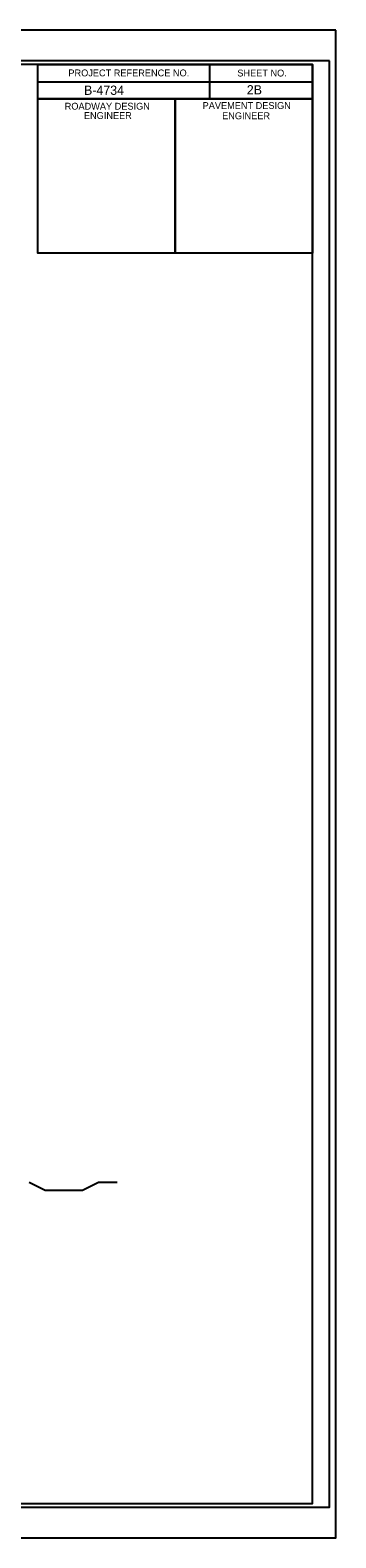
# Model space of a CAD drawing. Extents: x 1818040 to 1825768, y 638918 to 648046.
# Drawn here: x 1821878 to 1822100, y 642603 to 643703 of the extents above; entities that cross this region are included whole.
import ezdxf

# ---------------------------------------------------------------- set-up
doc = ezdxf.new("R2010")
doc.units = 0
for name, color, linetype in [('Sheet Data Field CELL', 7, 'Continuous'), ('Sheet Plot Border Inside CELL', 7, 'Continuous'), ('Sheet Plot Border Outside CELL', 7, 'Continuous'), ('Sheet Typical CELL', 7, 'Continuous'), ('Typical Slope Point Local CELL', 7, 'Continuous')]:
    doc.layers.add(name, color=color, linetype=linetype)

msp = doc.modelspace()

# ---------------------------------------------------------------- linework, layer by layer
at = {"layer": 'Sheet Plot Border Inside CELL'}
msp.add_lwpolyline([(1822095.8, 643680.8), (1820429.3, 643680.8), (1820429.3, 642625.7), (1822095.8, 642625.7)], close=True, dxfattribs=at)
at = {"layer": 'Sheet Plot Border Outside CELL'}
msp.add_lwpolyline([(1822100.3, 643703.3), (1820416.3, 643703.3), (1820416.3, 642603.3), (1822100.3, 642603.3)], close=True, dxfattribs=at)
at = {"layer": 'Sheet Typical CELL'}
for p, q in [((1822100.3, 643703.3), (1820416.3, 643703.3)), ((1822008.3, 643678.2), (1822008.3, 643653.2)), ((1821883.3, 643665.7), (1822083.3, 643665.7)), ((1821983.3, 643653.2), (1821983.3, 643540.8)), ((1820416.3, 642603.3), (1822100.3, 642603.3))]:
    msp.add_line(p, q, dxfattribs=at)
for points in [[(1822083.3, 643678.3), (1820583.3, 643678.3), (1820583.3, 642628.3), (1822083.3, 642628.3)], [(1821883.3, 643678.3), (1822083.3, 643678.3), (1822083.3, 643653.2), (1821883.3, 643653.2)], [(1821883.3, 643653.2), (1821983.3, 643653.2), (1821983.3, 643540.7), (1821883.3, 643540.7)], [(1821983.3, 643653.2), (1822083.3, 643653.2), (1822083.3, 643540.7), (1821983.3, 643540.7)]]:
    msp.add_lwpolyline(points, close=True, dxfattribs=at)
at = {"layer": 'Typical Slope Point Local CELL'}
msp.add_lwpolyline([(1821876.9, 642862.7), (1821880.8, 642860.8), (1821884.7, 642858.8), (1821888.6, 642856.9), (1821892.4, 642856.9), (1821896.3, 642856.9), (1821900.2, 642856.9), (1821904.1, 642856.9), (1821908, 642856.9), (1821911.9, 642856.9), (1821915.8, 642856.9), (1821919.7, 642858.8), (1821923.6, 642860.8), (1821927.5, 642862.7), (1821933.3, 642862.7), (1821937.2, 642862.7), (1821941.1, 642862.7)], dxfattribs=at)

# ---------------------------------------------------------------- texts
at = {"layer": 'Sheet Data Field CELL'}
for s, p in [('B-4734   ', (1821916.9, 643656.1)), ('2B ', (1822035.5, 643656.4))]:
    msp.add_text(s, height=6.75, dxfattribs=at).set_placement(p)
at = {"layer": 'Sheet Typical CELL'}
for s, p in [('PROJECT REFERENCE NO.', (1821905.5, 643669.6)), ('SHEET NO.', (1822028.6, 643669.5)), ('ROADWAY DESIGN', (1821902.8, 643645.3)), ('ENGINEER', (1821916.8, 643638.5)), ('PAVEMENT DESIGN', (1822003.3, 643645.8)), ('ENGINEER', (1822017.5, 643638.3))]:
    msp.add_text(s, height=5, dxfattribs=at).set_placement(p)

doc.saveas('drawing.dxf')
